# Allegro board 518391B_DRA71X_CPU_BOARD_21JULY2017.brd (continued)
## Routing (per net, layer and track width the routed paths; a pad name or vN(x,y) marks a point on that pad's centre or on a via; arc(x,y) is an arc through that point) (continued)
H_MCASP4_FSX: length 71.1
  TOP w0.127: v2(42.67,82.8) 44.45,82.8 45.09,82.17 45.09,75.95 42.93,73.79 v2(42.93,65.28) ; v2(74.55,71.12) 78.23,71.12 78.9,71.79 81.22,71.79 83.65,74.23 83.65,74.55 83.92,74.82 83.92,76.28 84.2,76.57 84.2,76.96 84.8,77.56 U27.B25
  LY4 w0.133: v2(74.55,71.12) 73.53,71.12 71.83,69.42 71.16,69.42 69.09,67.35 67.86,67.35 64.41,63.9 46.17,63.9 45.3,64.77 43.43,64.77 v2(42.93,65.28)
  BOTTOM w0.127: R256.2 v2(42.67,82.8)
H_MCASP5_ACLKX: length 71.7
  TOP w0.127: U21.7 v2(151.84,121.22)
  LY3 w0.133: v2(111.25,94.49) 112.52,95.76 122.94,95.76 123.23,96.05 125.14,96.05 125.86,96.77 127.51,96.77 128.4,95.88 129.54,95.88 130.05,96.39 131.06,96.39 131.57,95.88 v2(132.33,95.88)
  LY4 w0.133: v2(132.33,95.88) 132.33,97.15 132.84,97.66 132.84,120.78 136.14,124.08 149.73,124.08 151.84,121.98 v2(151.84,121.22)
  BOTTOM w0.127: R429.1 v2(111.25,94.49)
H_MCASP5_AXR0: length 85
  TOP w0.127: U27.AA5 v1(98.49,90.23) ; U21.8 v2(150.84,121.22)
  LY3 w0.133: v1(98.49,90.23) 98.49,93.03 101.6,96.14 106.55,96.14 106.68,96.01 111.25,96.01 111.89,96.65 122.17,96.65 123.06,97.54 128.02,97.54 128.4,97.16 131.57,97.16 131.91,96.82 v2(132.84,96.82)
  LY4 w0.133: v2(150.84,121.22) 150.84,122.34 150.11,123.06 135.64,123.06 133.22,120.65 133.22,97.2 v2(132.84,96.82)
H_MCASP5_AXR1: length 84.8
  TOP w0.102: 101.52,92.44 101.27,92.18 100.57,92.18 100.44,92.06 100.44,91.68 100.29,91.54 99.14,91.54 U27.AC4
  TOP w0.127: v2(101.98,92.9) 101.52,92.44 ; U21.5 v2(153.84,121.22)
  LY3 w0.133: v2(135.76,95.39) 131.56,95.39 131.02,95.93 130.13,95.93 129.7,95.5 128.14,95.5 127.25,96.39 126.11,96.39 124.71,95 121.54,95 121.12,95.42 117.13,95.42 116.71,95 112.52,95 111.51,93.98 108.84,93.98 108.46,94.36 102.87,94.36 101.98,93.47 v2(101.98,92.9)
  LY4 w0.133: v2(153.84,121.22) 153.84,121.2 152.27,119.63 137.79,119.63 136.91,118.75 135.77,118.75 135.64,118.61 135.64,101.98 135.76,101.85 v2(135.76,95.39)
H_MCASP5_FSX: length 89.2
  TOP w0.127: U21.6 v2(152.84,121.22) ; v1(97.84,87.63) U27.U6
  LY3 w0.133: v2(132.72,88.39) 125.72,88.39 125.27,88.84 120.48,88.84 119.52,87.88 113.53,87.88 112.76,88.65 105.3,88.65 105.3,88.65 104.52,88.65 102.74,86.87 98.61,86.87 v1(97.84,87.63)
  LY4 w0.133: v2(132.72,88.39) 132.72,89.53 135.64,92.46 135.64,94.36 135.3,94.7 135.3,119.68 135.64,120.01 151.63,120.01 v2(152.84,121.22)
H_MCASP6_ACLKX_ACLKR: length 65.4
  TOP w0.127: R100.1 93.09,66.67 93.34,66.42 93.34,60.28 96.27,57.36 96.27,50.59 96.48,50.37 96.48,44.41 96.14,44.07 96.14,40 97.16,38.99 97.16,23.12 95.88,21.84 89.66,21.84 89.23,21.41 v2(87.33,21.41)
  LY3 w0.133: v2(87.33,21.41) 87.33,20.28 86.69,19.63 v2(86.69,14.1)
  BOTTOM w0.127: J19.87 v2(86.69,14.1)
H_MCASP6_AXR1: length 78.2
  TOP w0.102: 90.45,76.17 90.45,76.36 90.69,76.59 90.69,77.23 U27.B17
  TOP w0.127: 90.45,76.17 90.45,74.94 89.95,74.44 89.95,73.12 90.68,72.39 90.68,71.73 90.42,71.48 90.42,69.24 90.8,68.86 90.8,68.83 92.33,67.31 92.33,66.17 92.84,65.66 92.84,59.94 94.36,58.42 94.36,56.9 95.25,56.01 95.25,40.05 96.65,38.65 96.65,23.33 95.67,22.35 86.87,22.35 v2(86.61,22.61)
  LY3 w0.133: v2(86.61,22.61) 86.61,20.32 86.09,19.79 v2(86.09,14.6)
  BOTTOM w0.127: J19.88 v2(86.09,14.6)
H_MCASP6_FSX_FSR: length 79.6
  TOP w0.102: U27.B18 90.04,77.23 90.04,76.71 89.95,76.61 89.95,76.17
  TOP w0.127: 89.95,76.17 89.95,75.15 89.44,74.65 89.44,74.24 88.82,73.61 88.82,72.22 89.66,71.37 89.66,69.21 91.44,67.44 91.44,59.06 94.74,55.75 94.74,39.83 96.14,38.44 96.14,23.54 95.46,22.86 88.39,22.86 87.88,23.37 85.85,23.37 v2(85.34,22.86)
  LY3 w0.133: v2(85.34,22.86) 84.96,22.48 84.96,20.95 85.49,20.43 v2(85.49,14.1)
  BOTTOM w0.127: J19.89 v2(85.49,14.1)
H_MCASP7_ACLKX_ACLKR: length 68.5
  TOP w0.127: R102.1 95.63,65.28 97.16,63.75 97.16,58.93 97.54,58.55 97.54,52.32 98.34,51.52 98.34,44.21 97.41,43.29 97.41,40.58 98.55,39.43 98.55,22.58 96.54,20.57 91.69,20.57 91.06,19.94 87.25,19.94 87.12,19.81 v2(83.95,19.81)
  LY3 w0.133: v2(83.69,14.6) 83.69,16.89 83.95,17.14 v2(83.95,19.81)
  BOTTOM w0.127: J19.92 83.69,13.96 83.69,13.97 v2(83.69,14.6)
H_MCASP7_AXR0: length 6.4
  TOP w0.127: v2(82.3,22.61) RJ30.1
  BOTTOM w0.127: J19.31 84.89,20.02 v2(82.3,22.61)
H_MCASP7_AXR1: length 87.6
  TOP w0.127: U27.E17 v1(90.04,79.18)
  LY3 w0.102: 89.79,76.17 89.79,76.58 89.03,77.34 89.03,78.74 89.14,78.85 89.71,78.85 v1(90.04,79.18)
  LY3 w0.133: 89.79,76.17 89.79,69.98 96.77,62.99 96.77,57.06 v2(98.97,54.86) ; v2(84.29,14.1) 84.29,16.09 84.45,16.26 84.45,20.07 84.07,20.45 v2(84.07,22.22)
  BOTTOM w0.127: J19.91 v2(84.29,14.1) ; v2(98.97,54.86) 98.81,54.7 98.81,53.85 103.12,49.53 103.12,48.26 104.52,46.86 104.52,40.89 100.33,36.7 100.33,30.35 96.39,26.42 91.06,26.42 88.27,23.62 86.87,23.62 85.47,22.22 v2(84.07,22.22)
H_MCASP7_FSX_FSR: length 80.8
  TOP w0.127: U27.F16 v1(91.34,79.83)
  LY3 w0.102: 90.42,76.17 90.42,78.92 v1(91.34,79.83)
  LY3 w0.133: v4(92.06,74.42) 91.44,74.42 90.42,75.44 90.42,76.17 ; v2(84.07,25.27) 84.58,24.76 84.58,20.7 84.89,20.4 v2(84.89,14.6)
  BOTTOM w0.127: v2(84.07,25.27) 86.49,25.27 100.33,39.12 100.33,43.05 98.98,44.4 98.98,48.21 95.88,51.31 95.88,58.29 95,59.18 95,63.5 92.52,65.98 92.52,73.98 92.08,74.42 v4(92.06,74.42) ; J19.90 v2(84.89,14.6)
H_MCU_DCAN1_STB: length 97.6
  TOP w0.102: 102.05,85.04 100.44,85.04 U27.P2
  TOP w0.127: 102.05,85.04 102.69,85.67 106.85,85.67 106.89,85.7 109.88,85.7 111.25,84.33 112.78,84.33 114.05,83.06 117.73,83.06 119.89,80.9 125.35,80.9 125.98,81.53 127.89,81.53 128.52,80.9 v2(131.32,80.9) ; R426.1 v2(137.16,26.29)
  LY4 w0.133: v2(131.32,80.9) 131.1,80.68 131.1,70.57 132.59,69.09 132.59,61.09 135,58.67 135.89,58.67 v2(139.95,54.61)
  BOTTOM w0.127: v2(139.95,54.61) 142.88,51.69 142.88,42.67 141.48,41.27 141.48,37.97 139.7,36.19 139.7,34.04 138.05,32.38 138.05,27.05 137.29,26.29 v2(137.16,26.29)
H_MCU_GPIO_1: length 65.4
  TOP w0.127: v2(127.76,80.9) 127.38,81.28 126.11,81.28 125.48,80.64 119.63,80.64 118.36,81.91 115.57,81.91 114.93,82.55 112.27,82.55 110.05,84.77 106.5,84.77 105.85,85.42 102.94,85.42 102.23,84.71 U27.N1
  LY4 w0.133: v2(127.76,80.9) 127.76,76.58 129.8,74.54 129.8,51.06 v2(126.87,48.13)
  BOTTOM w0.127: R327.1 v2(126.87,48.13)
H_MCU_GPIO_2: length 67.7
  TOP w0.127: U27.P1 101.87,85.36 102.43,85.92 106.75,85.92 106.78,85.96 110.13,85.96 111.38,84.71 113.16,84.71 114.43,83.44 117.86,83.44 120.14,81.15 125.1,81.15 125.73,81.79 128.4,81.79 v2(128.78,81.41)
  LY4 w0.133: v2(126.87,47.12) 126.87,47.54 130.06,50.72 130.06,74.79 128.78,76.07 v2(128.78,81.41)
  BOTTOM w0.127: R331.1 v2(126.87,47.12)
H_MCU_GPIO_3: length 76.9
  TOP w0.127: U27.N3 v1(99.79,84.38)
  LY3 w0.133: v1(99.79,84.38) 100.1,84.07 100.71,84.07 102.15,82.64 105.93,82.64 106.37,82.2 111.67,82.2 112.27,82.8 112.27,83.31 112.78,83.82 113.54,83.82 113.92,83.44 118.36,83.44 120.4,81.41 124.97,81.41 127.13,83.57 v2(128.78,83.57)
  LY4 w0.133: v2(128.78,83.57) 129.79,82.55 129.79,77.98 129.29,77.47 129.29,76.2 130.32,75.16 130.32,50.6 127.51,47.79 127.51,46.35 126.87,45.72 126.62,45.72 v2(125.98,45.08)
  BOTTOM w0.127: R335.1 127.38,46.1 127,45.72 126.62,45.72 v2(125.98,45.08)
H_MCU_GPIO_4: length 77.1
  TOP w0.127: U27.N4 v1(99.14,84.38)
  LY3 w0.133: v1(99.14,84.38) 99.51,84.76 100.54,84.76 101.73,83.57 104.77,83.57 105.15,83.19 105.92,83.19 106.05,83.31 110.36,83.31 111.38,84.33 113.66,84.33 114.17,83.82 118.62,83.82 120.65,81.79 124.71,81.79 127.25,84.33 v2(129.41,84.33)
  LY4 w0.133: v2(129.41,84.33) 130.18,83.57 130.18,77.6 129.67,77.09 129.67,76.45 130.58,75.54 130.58,49.43 129.79,48.64 129.03,48.64 127.77,47.38 127.77,45.98 v2(126.87,45.08)
  BOTTOM w0.127: R341.1 v2(126.87,45.08)
H_MMC1_CLK: length 67
  TOP w0.127: v2(149.61,89.03) 149.35,88.77 140.84,88.77 139.19,90.42 136.4,90.42 134.87,88.9 132.63,88.9 131.07,87.34 119.6,87.34 118.75,86.49 R66.1
  LY4 w0.133: v2(149.48,113.92) 149.48,112.9 150.75,111.63 150.75,106.43 151.38,105.79 151.38,102.23 149.22,100.08 149.22,94.74 149.86,94.11 149.86,89.28 v2(149.61,89.03)
  BOTTOM w0.127: RU1.12 149.41,113.85 v2(149.48,113.92) R226.2
H_MMC1_CMD: length 76.7
  TOP w0.127: U27.V4 v1(99.14,88.28)
  LY3 w0.133: v2(146.18,89.53) 145.67,89.03 143.64,89.03 141.99,90.68 135.25,90.68 135,90.42 123.57,90.42 122.84,89.7 114.08,89.7 114.05,89.66 103,89.66 101.22,87.88 99.54,87.88 v1(99.14,88.28)
  LY4 w0.133: v2(146.18,89.53) 146.18,92.46 146.59,92.87 146.59,99.98 147.11,100.5 147.11,111.55 147.46,111.9 v2(147.46,113.65)
  BOTTOM w0.127: R227.2 147.45,113.66 v2(147.46,113.65) RU1.9
H_MMC1_D0: length 74.4
  TOP w0.127: v1(99.79,88.28) U27.V3
  LY3 w0.133: v2(144.78,89.53) 143.26,91.06 135,91.06 134.75,90.8 123.19,90.8 122.94,91.06 116.17,91.06 116.13,91.02 115.78,91.02 115.73,91.06 113.79,91.06 113.41,90.68 106.3,90.68 105.79,90.17 103,90.17 101.11,88.28 v1(99.79,88.28)
  LY4 w0.133: v2(143.45,105.03) 143.45,103.66 143.61,103.5 145.13,103.5 145.29,103.35 145.29,103.13 145.13,102.97 144.79,102.97 144.65,102.84 144.65,100.18 144.81,100.03 145.13,100.03 145.29,99.87 145.29,99.65 145.13,99.49 144.81,99.49 144.65,99.34 144.65,99.12 144.81,98.96 145.13,98.96 145.29,98.8 145.29,98.58 145.13,98.43 144.81,98.43 144.65,98.27 144.65,98.01 144.79,97.88 145,97.88 145.16,97.72 145.16,97.5 145,97.34 144.56,97.34 144.4,97.19 144.4,96.97 144.56,96.81 145,96.81 145.16,96.65 145.16,96.43 145,96.28 144.56,96.28 144.4,96.12 144.4,95.9 144.56,95.74 145,95.74 145.16,95.59 145.16,95.37 145,95.21 144.56,95.21 144.4,95.05 144.4,94.83 144.56,94.68 145,94.68 145.16,94.52 145.16,94.3 145,94.14 144.56,94.14 144.4,93.99 144.4,93.73 144.65,93.47 144.65,92.71 145.29,92.07 145.29,90.04 v2(144.78,89.53)
  BOTTOM w0.127: RU2.4 v2(143.45,105.03) 143.45,104.47 143.38,104.39 R228.2
H_MMC1_D1: length 79.5
  TOP w0.102: 101.52,88.51 101.3,88.29 100.44,88.29 U27.V2
  TOP w0.127: 101.52,88.51 112.13,88.51 113.39,87.25 118.36,87.25 119.13,88.01 121.29,88.01 121.54,88.27 130.56,88.27 132.59,90.3 135.13,90.3 135.76,90.93 142.49,90.93 v2(142.88,90.55)
  LY4 w0.133: v2(141.5,104.8) 141.5,102.97 141.99,102.49 141.99,99.35 142.14,99.2 143.63,99.2 143.76,99.06 143.76,98.8 143.63,98.66 142.14,98.66 141.99,98.51 141.99,98.29 142.14,98.13 143.73,98.13 143.89,97.97 143.89,97.75 143.73,97.6 142.14,97.6 141.99,97.44 141.99,97.22 142.14,97.06 143.73,97.06 143.89,96.91 143.89,96.69 143.73,96.53 142.14,96.53 141.99,96.37 141.99,96.15 142.14,96 143.73,96 143.89,95.84 143.89,95.62 143.73,95.46 142.14,95.46 141.99,95.31 141.99,95.09 142.14,94.93 143.73,94.93 143.89,94.77 143.89,94.55 143.73,94.4 142.14,94.4 141.99,94.24 141.99,93.98 142.88,93.09 v2(142.88,90.55)
  BOTTOM w0.127: R230.2 141.48,104.78 v2(141.5,104.8) RU2.7
H_MMC1_D2: length 81
  TOP w0.127: U27.W1 101.19,88.61 101.35,88.77 112.4,88.77 113.66,87.5 118.11,87.5 118.87,88.27 121.03,88.27 121.41,88.65 121.78,88.65 121.93,88.79 121.93,89.01 122.08,89.15 122.29,89.15 122.44,89.01 122.44,88.79 122.58,88.65 122.79,88.65 122.94,88.79 122.94,89.01 123.09,89.15 123.3,89.15 123.45,89.01 123.45,88.79 123.6,88.65 123.81,88.65 123.96,88.79 123.96,89.01 124.11,89.15 124.32,89.15 124.47,89.01 124.47,88.79 124.62,88.65 124.83,88.65 124.98,88.79 124.98,89.01 125.12,89.15 125.33,89.15 125.48,89.01 125.48,88.79 125.63,88.65 125.84,88.65 125.99,88.79 125.99,89.01 126.14,89.15 126.35,89.15 126.5,89.01 126.5,88.79 126.65,88.65 128.05,88.65 128.2,88.79 128.2,89.51 128.35,89.66 128.56,89.66 128.71,89.51 128.71,88.79 128.86,88.65 129.07,88.65 129.22,88.79 129.22,89.51 129.37,89.66 129.58,89.66 129.73,89.51 129.73,88.79 129.88,88.65 130.3,88.65 132.21,90.55 134.87,90.55 135.51,91.19 143,91.19 143.64,90.55 148.72,90.55 v2(149.35,89.92)
  LY4 w0.133: v2(149.35,89.92) 149.35,90.8 149.6,91.05 149.6,93.61 148.84,94.36 148.84,97.69 148.69,97.84 147.73,97.84 147.57,98 147.57,98.22 147.73,98.38 148.69,98.38 148.84,98.53 148.84,98.75 148.69,98.91 147.73,98.91 147.57,99.07 147.57,99.29 147.73,99.44 148.69,99.44 148.84,99.6 148.84,100.06 150.69,101.91 150.69,104.07 v2(150.06,104.7)
  BOTTOM w0.127: R231.2 150.11,104.65 v2(150.06,104.7) RU1.4
H_MMC1_D3: length 80.1
  TOP w0.127: v2(147.19,89.53) 146.69,89.03 143.51,89.03 142.62,89.92 141.99,89.92 141.22,90.68 136.02,90.68 135.25,89.92 132.84,89.92 130.68,87.76 119.38,87.76 118.62,86.99 113.16,86.99 111.89,88.26 101.72,88.26 101.42,87.96 U27.V1
  LY4 w0.133: v2(148.11,104.93) 148.11,103.35 148.21,103.25 148.21,100.84 147.07,99.69 147.07,97.47 147.22,97.32 148.18,97.32 148.34,97.16 148.34,96.94 148.18,96.78 147.22,96.78 147.07,96.63 147.07,96.41 147.22,96.25 148.18,96.25 148.34,96.09 148.34,95.87 148.18,95.72 147.22,95.72 147.07,95.56 147.07,95.34 147.22,95.18 148.18,95.18 148.34,95.03 148.34,94.81 148.18,94.65 147.22,94.65 147.07,94.49 147.07,94.23 147.59,93.71 147.59,93.65 147.75,93.49 148.43,93.49 148.59,93.33 148.59,93.11 148.06,92.58 146.94,92.58 146.72,92.36 146.72,92.17 146.94,91.95 147.7,91.95 147.95,91.69 147.95,91.19 147.7,90.93 147.07,90.93 146.81,90.68 146.81,90.42 147.03,90.21 147.69,90.21 147.94,89.96 147.94,89.78 147.69,89.53 v2(147.19,89.53)
  BOTTOM w0.127: R229.2 148.08,104.9 v2(148.11,104.93) RU1.7
H_MMC1_SDCD: length 84.4
  TOP w0.127: U27.U5 v1(98.49,87.64)
  LY3 w0.133: v2(129.03,125.73) 130.56,127.25 141.6,127.25 v2(143.13,125.73) ; v2(127.63,89.41) 127.37,89.15 114.27,89.15 114.26,89.14 103.75,89.14 101.85,87.25 98.88,87.25 v1(98.49,87.64)
  LY4 w0.133: v2(129.03,125.73) 128.02,124.71 128.02,89.79 v2(127.63,89.41)
  BOTTOM w0.127: R410.2 v2(143.13,125.73) R411.1
H_MMC1_SDWP: length 69.5
  TOP w0.127: U27.V5 v1(98.49,88.28)
  LY3 w0.133: v1(98.49,88.28) 99.27,87.5 101.34,87.5 103.24,89.4 114.15,89.4 114.16,89.41 123.7,89.41 124.45,90.16 135.11,90.16 135.12,90.17 135.38,90.17 135.63,90.42 140.6,90.42 v2(140.84,90.17)
  LY4 w0.133: v2(140.84,90.17) 140.84,90.81 140.63,91.02 140.63,94.02 140.85,94.24 v2(140.85,113.66)
  BOTTOM w0.127: RU2.9 v2(140.85,113.66)
H_MMC1_SELN: length 90.9
  TOP w0.102: 101.52,84.38 100.44,84.38 U27.N2
  TOP w0.127: v2(146.35,78.99) 145.58,78.23 136.14,78.23 133.99,80.39 119.51,80.39 118.62,81.28 105.46,81.28 102.36,84.38 101.52,84.38
  LY3 w0.133: v2(152.02,107.7) 151.64,107.31 145.8,107.31 145.43,107.69 v2(145.4,107.69)
  LY4 w0.133: v2(146.35,78.99) 146.35,80.35 145.67,81.03 145.67,101.22 146.22,101.77 146.22,103.59 145.41,104.39 145.41,107.68 v2(145.4,107.69)
  BOTTOM w0.127: v2(152.02,107.7) 152.02,106.37 RU1.1 152.01,104.76 151.76,104.52 R425.1 ; RU2.1 v2(145.4,107.69)
H_NMIN_DSP: length 16.2
  TOP w0.102: 84.4,82.8 84.47,82.8 84.76,83.09 85.49,83.09 U27.L24
  TOP w0.127: 84.4,82.8 82.59,82.8 81.07,81.28 78.78,81.28 76.66,79.16 76.53,79.16 75.48,78.1 73.03,78.1 R71.2
H_PMIC_INTN: length 125.9
  TOP w0.127: U32.26 82.97,51.85 82.47,51.36 81.76,51.36 81.46,51.05 77.47,51.05 v2(77.34,51.18) ; U27.AB10 v1(95.24,90.88) ; v2(113.03,56.26) 113.03,58.29 112.39,58.93 v2(112.39,63.25)
  LY3 w0.133: v2(96.77,96.39) 98.04,97.66 106.55,97.66 106.72,97.83 v2(118.87,97.83) ; v2(113.03,56.26) 112.14,55.37 111.51,55.37 106.92,50.79 96.76,50.79 96.39,50.42 89.03,50.42 88.13,51.31 88.13,51.82 87.78,52.18 82.91,52.18 81.91,51.18 v2(77.34,51.18)
  LY4 w0.133: v2(112.39,63.25) 115.95,63.25 118.62,65.91 118.62,77.72 116.97,79.38 116.97,83.44 117.73,84.2 117.73,89.03 116.84,89.92 116.84,90.8 118.87,92.83 118.87,97.78 118.87,97.79 v2(118.87,97.83) ; v1(95.24,90.88) 95.7,91.34 95.7,94.43 96.77,95.5 v2(96.77,96.39)
  BOTTOM w0.127: v2(96.77,96.39) 97.03,96.14 R236.1
H_PORZ: length 106.7
  TOP w0.127: U27.F19 v1(89.39,79.83) ; v2(85.34,68.96) 85.34,68.07 85.98,67.44 85.98,65.91 86.61,65.28 89.68,65.28 90.42,64.54 90.42,58.42 93.73,55.12 93.73,52.79 93.56,52.62 v2(93.56,50.93) 93.56,49.95 93.73,49.78 93.73,41.4 93.47,41.15 v2(93.47,38.99) ; TP40.1 74.88,51.74 78.56,51.74 78.94,51.36 81.38,51.36 81.64,51.61 82.22,51.61 82.47,51.86 U32.25 ; U40.3 116.47,41.39 115.06,42.8 113.41,42.8 111.38,40.77 v2(111.38,37.68)
  LY3 w0.133: TP40.1 75.18,52.19 77.98,52.19 78.49,51.69 81.91,51.69 82.66,52.44 87.91,52.44 88.39,51.96 88.39,51.56 89.03,50.93 v2(93.56,50.93) ; v2(111.38,37.68) 110.15,37.68 109.09,38.73 96.52,38.73 96.27,38.99 v2(93.47,38.99)
  BOTTOM w0.102: 87.58,76.17 88.82,77.42 88.82,79.27 v1(89.39,79.83)
  BOTTOM w0.127: 87.58,76.17 85.85,74.45 85.85,69.47 v2(85.34,68.96)
H_RSTOUTN: length 150.4
  TOP w0.127: TP36.1 74.55,62.1 74.93,61.72 79.88,61.72 81.41,60.2 81.41,59.56 81.69,59.28 U32.13 ; TP36.1 74.55,69.18 v2(74.42,69.3) ; TP36.1 R104.2 ; U27.E20 v1(88.09,79.18)
  LY3 w0.133: v2(145.92,62.61) 145.03,63.5 137.29,63.5 136.65,62.86 134.62,62.86 134.51,62.98 124.85,62.98 124.21,63.63 123.06,63.63 122.86,63.83 122,63.83 121.78,63.62 121.78,63.24 121.54,62.99 113.67,62.99 v2(111.89,64.77)
  LY4 w0.133: v2(111.89,64.77) 106.3,64.77 105.41,63.88 76.96,63.88 76.33,63.25 TP36.1 ; v2(74.42,69.3) 74.42,69.84 76.33,71.74 76.33,72.64 76.88,73.2 81.15,73.2 81.23,73.28 81.85,73.28 82.26,73.69 82.49,73.69 83.4,74.6 84.03,74.6 84.6,75.16 85.32,75.16 85.32,75.16 85.45,75.16 86.49,76.2 86.49,76.33 88.46,78.3 88.46,78.81 v1(88.09,79.18) ; v2(141.66,92.64) 141.66,82.75 144.78,79.63 144.78,76.2 146.18,74.8 146.18,70.48 145.8,70.1 145.8,63.25 145.92,63.12 v2(145.92,62.61)
  BOTTOM w0.127: J21.29 v2(141.66,92.64)
  BOTTOM w0.14: U54.1 115.3,64.02 114.55,64.77 v2(111.89,64.77)
H_SPI1_CS0: length 69.7
  TOP w0.102: 84.79,76.17 84.79,77.06 84.96,77.23 85.32,77.23 85.64,77.56 U27.B24
  TOP w0.127: 84.79,76.17 84.79,75.32 83.91,74.45 83.91,74.12 81.32,71.54 79.33,71.54 78.44,70.66 76.18,70.66 76.01,70.48 74.24,70.48 74.08,70.65 v2(74.04,70.65) ; v2(40.39,69.72) 40.39,67.82 40.13,67.56 40.13,62.86 37.59,60.32 37.59,57.4 36.58,56.39 34.16,56.39 33.07,55.29 U36.43
  LY3 w0.133: v2(74.04,70.65) 73.19,71.5 65.28,71.5 64.43,70.65 41.31,70.65 v2(40.39,69.72)
H_SPI1_CS1: length 51.4
  TOP w0.127: v2(72.39,72.35) 72.95,71.79 77.51,71.79 77.85,72.14 77.85,72.64 78.14,72.94 80.46,72.94 83.01,75.49 83.01,77 83.41,77.4 83.88,77.4 84.69,78.21 U27.C25 ; U34.23 51.91,53.3 54.1,55.5 54.99,55.5 55.5,56.01 55.5,64.52 v2(55.88,64.9)
  LY4 w0.133: v2(55.88,64.9) 56.82,65.84 62.92,65.84 66.17,69.09 68.62,69.09 69.6,70.07 69.6,70.51 71.69,72.6 72.14,72.6 v2(72.39,72.35)
H_SPI1_D0: length 71.3
  TOP w0.127: v2(73.53,72.35) 74.08,72.9 75.48,72.9 75.91,72.9 76.45,73.44 79.29,73.44 81.47,75.63 82.11,75.63 82.42,75.95 82.42,77.13 83.27,77.98 83.69,77.98 84.57,78.86 U27.D25 ; v2(57.4,64.9) 56.26,63.75 56.26,56.01 52.96,52.7 52.7,52.7 52.3,52.3 v2(52.09,52.3) U34.21 ; U36.41 v2(33.08,53.78)
  LY4 w0.133: v2(57.4,64.9) 57.83,65.32 64.18,65.32 67.25,68.39 68.66,68.39 70.12,69.86 70.12,70 71.71,71.59 72.24,71.59 72.69,72.03 72.69,72.03 73.01,72.35 73.53,72.35 v2(73.53,72.35)
  BOTTOM w0.127: v2(33.08,53.78) 40.06,53.78 40.51,54.23 v2(41.53,54.23) 49.78,54.23 51.71,52.3 v2(52.09,52.3)
H_SPI1_D1: length 71.1
  TOP w0.102: 84.4,78.31 84.63,78.53 85.49,78.53 U27.D24
  TOP w0.127: U34.20 52.57,51.8 v2(52.96,52.2) 56.64,55.88 56.64,63.37 v2(58.17,64.9) ; v2(74.3,72.26) 75.63,72.26 76.56,73.19 79.53,73.19 81.71,75.38 82.21,75.38 82.76,75.92 82.76,77.11 83.37,77.72 83.82,77.72 84.4,78.31 ; U36.40 v2(34.96,53.28)
  LY4 w0.133: v2(58.17,64.9) 58.33,65.06 64.28,65.06 67.36,68.13 68.77,68.13 70.38,69.75 70.38,69.89 71.82,71.33 72.35,71.33 72.95,71.93 73.7,71.93 74.04,72.26 v2(74.3,72.26)
  BOTTOM w0.127: v2(52.96,52.2) 52.65,51.88 51.62,51.88 49.78,53.72 v2(40.89,53.72) 40.45,53.28 v2(34.96,53.28)
H_SPI1_SCLK: length 60.8
  TOP w0.127: U34.22 52.17,52.8 v2(52.45,53.09) 52.96,53.09 55.88,56.01 55.88,64.13 v2(56.64,64.9) ; U36.42 v2(34.96,54.28) ; v2(71.75,72.01) 72.22,71.54 78.02,71.54 78.74,72.26 R81.2
  LY4 w0.133: v2(56.64,64.9) 57.32,65.58 64.06,65.58 67.13,68.65 68.55,68.65 69.86,69.96 69.86,70.12 v2(71.75,72.01)
  BOTTOM w0.127: v2(52.45,53.09) 52.2,52.83 51.82,52.83 49.91,54.74 v2(42.16,54.74) 40.39,54.74 39.93,54.28 v2(34.96,54.28)
H_SPI2_CS0: length 87.4
  TOP w0.102: 84.4,79.77 84.47,79.83 85.49,79.83 U27.F24
  TOP w0.127: 84.4,79.77 83.38,78.74 82.91,78.74 81.51,77.34 79.25,77.34 78.66,76.76 78.66,76 76.87,74.21 76.14,74.21 76.1,74.17 76.09,74.17 75.59,73.66 73.6,73.66 73.22,73.28 71.54,73.28 70.74,72.47 70.74,69.89 71.12,69.51 71.12,64.3 70.74,63.92 70.74,63.29 69.22,61.76 69.22,53.85 72.14,50.93 v2(72.14,44.07)
  LY3 w0.133: v2(72.14,44.07) 73.15,43.05 73.15,40.51 76.45,37.21 76.45,36.83 79.63,33.65 79.63,30.61 87.76,22.48 87.76,20.07 87.38,19.68 87.38,18.41 87.89,17.9 v2(87.89,14.1)
  BOTTOM w0.127: J19.85 v2(87.89,14.1)
H_SPI2_D0: length 89.1
  TOP w0.102: U27.G24 85.5,80.49 85.5,80.49 85.49,80.48 84.4,80.48
  TOP w0.127: 84.4,80.48 84.29,80.48 83.06,79.25 79.65,79.25 78.74,78.34 78.74,77.79 77.22,76.26 77.22,75.56 76.37,74.71 75.93,74.71 75.89,74.68 75.88,74.68 75.38,74.17 73.39,74.17 73.01,73.79 71.33,73.79 70.23,72.68 70.23,69.68 70.61,69.3 70.61,64.51 70.23,64.13 70.23,63.5 68.71,61.97 68.71,53.59 71.37,50.93 71.37,47.62 v2(71.25,47.5)
  LY3 w0.133: v2(89.09,14.03) 89.03,14.09 89.03,18.16 88.9,18.29 88.9,22.35 80.39,30.86 80.39,34.92 73.91,41.4 73.91,43.56 71.75,45.72 71.75,46.99 v2(71.25,47.5)
  BOTTOM w0.127: J19.83 v2(89.09,14.03)
H_SPI2_D1: length 87.8
  TOP w0.127: U27.F25 84.35,80.16 83.19,78.99 79.76,78.99 78.99,78.23 78.99,77.68 77.47,76.16 77.47,75.44 76.49,74.46 76.03,74.46 75.99,74.42 75.99,74.42 75.48,73.91 73.49,73.91 73.11,73.53 71.44,73.53 70.48,72.58 70.48,69.79 70.87,69.41 70.87,64.41 70.48,64.03 70.48,63.39 68.96,61.87 68.96,53.72 71.75,50.93 71.75,46.99 v2(71.25,46.48)
  LY3 w0.133: v2(88.49,14.57) 88.52,14.6 88.52,22.22 80.01,30.73 80.01,34.8 73.53,41.27 73.53,43.43 71.25,45.72 v2(71.25,46.48)
  BOTTOM w0.127: J19.84 v2(88.49,14.57)
H_SPI2_SCLK: length 74.4
  TOP w0.127: v2(70.87,48.89) 70.87,51.05 68.45,53.47 68.45,62.08 69.98,63.6 69.98,64.24 70.36,64.62 70.36,69.2 69.98,69.58 69.98,72.79 71.23,74.04 71.44,74.04 72.77,74.04 73.41,74.68 R77.2
  LY3 w0.133: v2(70.87,48.89) 72.14,47.62 72.14,45.85 74.17,43.81 74.17,41.65 80.77,35.05 80.77,30.99 89.28,22.48 89.28,18.67 89.66,18.29 89.66,14.6 v2(89.69,14.58)
  BOTTOM w0.127: J19.82 v2(89.69,14.58)
H_SPI4_CS0: length 192
  TOP w0.127: v2(128.78,82.59) 125.39,82.59 124.46,81.66 120.65,81.66 118.11,84.2 114.55,84.2 112.65,86.11 111.63,86.11 110.66,87.08 106.24,87.08 106.22,87.07 105.74,87.07 105.16,86.49 101.98,86.49 101.5,86.01 U27.R1
  LY3 w0.133: v2(128.78,82.59) 131.15,82.59 135.52,78.22 153.84,78.22 156.36,75.69 165.1,75.69 167.39,73.41 167.39,64.77 164.08,61.47 164.08,60.45 163.5,59.87 163.5,57.96 161.04,55.5 161.04,54.48 160.15,53.59 160.15,43.56 161.42,42.29 161.42,26.67 152.53,17.78 117.47,17.78 112.27,12.57 106.17,12.57 104.14,14.6 v2(101.68,14.6)
  BOTTOM w0.127: J19.62 v2(101.68,14.6)
H_SPI4_CS1: length 200.1
  TOP w0.127: U27.N6 v1(97.84,84.38)
  LY3 w0.133: v2(100.71,14.1) 104.04,14.1 105.94,12.19 112.37,12.19 113.92,13.74 142.77,13.74 144.4,15.37 144.4,15.87 144.97,16.45 153.35,16.45 157.48,20.57 161.54,20.57 166.37,25.4 166.37,28.19 168.14,29.96 168.14,52.59 167.77,52.96 167.77,73.46 165.15,76.07 156.59,76.07 154.18,78.48 136.4,78.48 133.99,80.9 133.99,81.41 132.33,83.06 127.13,83.06 125.09,81.03 120.14,81.03 118.11,83.06 113.41,83.06 v2(113.16,83.31)
  LY4 w0.133: v2(113.16,83.31) 112.14,84.33 105.41,84.33 105.12,84.04 102.19,84.04 101.4,84.84 98.29,84.84 v1(97.84,84.38)
  BOTTOM w0.127: J19.64 100.46,12.81 100.46,13.84 v2(100.71,14.1)
H_SPI4_CS2: length 205.6
  TOP w0.102: U27.T4 99.12,86.36 101.34,86.36 101.52,86.54
  TOP w0.127: v4(105.16,87.14) 105.16,87.12 104.78,86.74 101.73,86.74 101.52,86.54
  LY3 w0.133: v2(99.85,14.12) 100.39,13.59 101.85,13.59 104.13,11.31 113.03,11.31 114.68,12.96 144.9,12.96 145.92,11.94 151.76,11.94 156.58,16.76 159.13,16.76 161.8,19.43 162.81,19.43 168.9,25.52 168.9,26.82 168.14,27.58 168.14,28.68 168.92,29.46 168.92,74.8 164.21,79.5 148.59,79.5 141.57,86.52 135.98,86.52 135.64,86.87 126.36,86.87 124.91,88.32 120.83,88.32 119.88,87.36 113.18,87.36 113.16,87.38 112.9,87.38 112.27,88.01 105.66,88.01 105.16,87.5 v4(105.16,87.14)
  BOTTOM w0.127: J19.65 99.88,14.1 v2(99.85,14.12)
H_SPI4_CS3: length 208.8
  TOP w0.102: 101.52,87.1 101.42,86.99 98.5,86.99 U27.T5
  TOP w0.127: v4(104.52,87.5) 104.27,87.75 102.18,87.75 101.52,87.1
  LY3 w0.133: v2(99.12,14.03) 100.08,13.08 101.6,13.08 103.63,11.05 113.28,11.05 114.94,12.7 144.53,12.7 145.67,11.56 154.56,11.56 162.05,19.05 163.19,19.05 169.29,25.15 169.29,26.8 168.4,27.69 168.4,28.57 169.29,29.46 169.29,74.93 164.34,79.88 148.84,79.88 140.33,88.39 135,88.39 134.53,87.93 125.82,87.93 125.16,88.58 120.59,88.58 119.63,87.62 113.29,87.62 112.52,88.39 105.41,88.39 v4(104.52,87.5)
  BOTTOM w0.127: J19.66 99.28,13.88 v2(99.12,14.03)
H_SPI4_D0: length 186.7
  TOP w0.102: 101.52,85.69 100.44,85.69 U27.R2
  TOP w0.127: 101.52,85.69 101.69,85.69 102.18,86.18 106.22,86.18 106.25,86.21 110.64,86.21 111.13,85.72 112.52,85.72 114.43,83.82 117.98,83.82 120.4,81.41 124.84,81.41 125.6,82.17 129.03,82.17 v2(129.29,81.91)
  LY3 w0.133: v2(129.29,81.91) 133.24,77.96 153.31,77.96 155.96,75.31 163.92,75.31 167,72.22 167,65.02 162.81,60.83 162.81,57.91 160.53,55.63 160.53,54.61 159.77,53.85 159.77,43.18 160.91,42.04 160.91,27.18 152.78,19.05 146.05,19.05 145.67,18.67 143.89,18.67 143.38,19.18 138.18,19.18 137.16,18.16 114.43,18.16 113.28,19.3 102.87,19.3 v2(102.62,19.56)
  BOTTOM w0.127: v2(102.62,19.56) 102.28,19.22 J19.60
H_SPI4_D1: length 196.3
  TOP w0.127: U27.P3 v1(99.79,85.68)
  LY3 w0.133: v1(99.79,85.68) 106.64,85.68 106.8,85.85 112.02,85.85 112.52,85.34 119.51,85.34 121.67,87.5 124.21,87.5 126.87,84.84 131.95,84.84 132.33,84.45 132.84,84.45 135.64,81.66 135.64,81.28 136.4,80.52 145.92,80.52 147.7,78.74 163.96,78.74 168.15,74.55 168.15,53.59 168.4,53.35 168.4,29.67 167.51,28.78 167.51,25.65 162.05,20.19 157.99,20.19 152.91,15.11 146.05,15.11 145.55,14.61 144.15,14.61 143.02,13.48 114.19,13.48 112.54,11.83 105.61,11.83 v2(104.65,12.79)
  BOTTOM w0.127: J19.61 v2(104.65,12.79)
H_SPI4_SCLK: length 187.8
  TOP w0.127: v2(116.84,85.85) 116.82,85.85 R183.1 ; v2(101.73,19.43) 103.12,18.03 v2(103.12,13.59)
  LY3 w0.133: v2(116.84,85.85) 119.38,85.85 121.28,87.76 121.3,87.76 121.3,87.76 124.31,87.76 124.32,87.76 124.46,87.76 127,85.22 132.21,85.22 132.59,84.84 133.86,84.84 136.27,82.42 144.65,82.42 147.95,79.12 164.08,79.12 168.53,74.68 168.53,54.48 168.66,54.36 168.66,29.57 167.77,28.68 167.77,25.4 162.18,19.81 160.4,19.81 158.5,17.91 156.59,17.91 152.59,13.91 146.11,13.91 145.8,14.22 144.4,14.22 143.4,13.22 114.45,13.22 112.8,11.57 104.51,11.57 103.12,12.95 v2(103.12,13.59)
  BOTTOM w0.127: J19.59 101.68,19.38 v2(101.73,19.43)
H_UART1_RXD: length 123.9
  TOP w0.127: v2(67.73,64.01) 67.31,64.43 67.31,73.51 69.72,75.92 69.72,77.34 70.36,77.98 72.52,77.98 72.9,78.36 75.37,78.36 76.43,79.41 76.56,79.41 78.68,81.53 80.96,81.53 82.48,83.05 84.42,83.05 84.78,83.41 U27.L25
  LY3 w0.133: v2(131.57,38.99) 131.57,37.46 130.81,36.7 130.81,35.31 127.76,32.26 122.68,32.26 121.29,30.87 101.59,30.87 100.97,31.5 86.75,31.5 75.93,42.32 75.93,45.48 74.3,47.12 74.3,48.26 69.48,53.07 69.48,61.71 68.07,63.12 68.07,63.67 v2(67.73,64.01)
  BOTTOM w0.127: R357.1 v2(131.57,38.99)
H_UART1_TXD: length 128
  TOP w0.127: U27.M25 84.75,84.06 84.25,83.56 82.27,83.56 80.75,82.04 78.47,82.04 76.35,79.92 76.21,79.92 75.41,79.12 70.78,79.12 68.8,77.13 68.8,75.4 67.06,73.66 67.06,63.63 v2(67.31,63.37)
  LY3 w0.133: v2(67.31,63.37) 69.09,61.59 69.09,52.96 73.91,48.13 73.91,46.99 75.67,45.23 75.67,42.14 86.7,31.11 100.71,31.11 101.22,30.61 121.92,30.61 123.19,31.88 130.94,31.88 132.21,33.15 132.21,36.74 132.04,36.91 132.04,38.31 v2(132.72,38.99)
  BOTTOM w0.127: R356.1 v2(132.72,38.99)
H_UART3_RXD_BOOT: length 106.3
  TOP w0.127: U27.N22 v1(86.79,84.38)
  LY4 w0.133: v2(46.1,99.44) 45.58,98.92 45.58,97.19 46.07,96.7 46.07,69.4 47.5,67.97 63.14,67.97 65.1,69.93 65.1,70.69 66.41,72 66.41,73.01 70.1,76.71 73.03,76.71 78.11,81.79 80.9,81.79 83.94,84.83 84.51,84.83 84.52,84.84 86.34,84.84 v1(86.79,84.38)
  BOTTOM w0.127: R232.1 23.75,102.74 41.27,102.74 44.58,99.44 v2(46.1,99.44)
H_UART3_TXD_BOOT: length 106.9
  TOP w0.102: 84.4,84.07 84.72,84.38 85.49,84.38 85.49,84.38 U27.N24
  TOP w0.127: R56.2 17.65,98.81 v4(18.01,98.44) ; 84.4,84.07 84.15,83.81 82.04,83.81 80.52,82.3 78.36,82.3 76.24,80.18 76.11,80.18 75.31,79.38 70.68,79.38 68.54,77.24 68.54,75.65 66.93,74.04 v2(65.91,74.04)
  LY4 w0.133: v2(65.91,74.04) 64.52,72.64 64.52,71.89 63.49,70.87 47.75,70.87 46.85,71.77 46.85,97.63 v2(46.69,97.79)
  BOTTOM w0.127: v4(18.01,98.44) 18.67,97.79 19.69,97.79 24.13,102.23 40.64,102.23 45.09,97.79 v2(46.69,97.79)
  BOTTOM w0.14: U52.2 v4(18.01,98.44)
H_UART5_CTSN: length 86.2
  TOP w0.102: 99.46,89.92 U27.AA3
  TOP w0.127: U27.AA3 v1(99.79,90.23) ; U21.62 v2(159.62,112.26)
  LY3 w0.133: v2(154.31,90.55) 153.03,91.82 145.92,91.82 145.29,91.19 144.14,91.19 143.64,91.69 134.62,91.69 134.37,91.44 123.95,91.44 121.92,93.47 121.03,93.47 120.02,94.49 112.65,94.49 111.58,93.42 108.89,93.42 108.33,93.98 103.25,93.98 102.4,93.13 102.4,92.72 101.52,91.84 99.92,90.23 v1(99.79,90.23)
  LY4 w0.133: v2(159.62,112.26) 160.15,111.73 160.15,110.24 160.45,109.93 160.45,95.68 156.72,91.95 155.7,91.95 v2(154.31,90.55)
H_UART5_RTSN: length 86.1
  TOP w0.102: U27.W2 100.44,88.93 101,88.93 101.08,89.02 101.52,89.02
  TOP w0.127: v2(152.65,89.66) 150.5,89.66 149.35,90.8 143.89,90.8 143.26,91.44 135.25,91.44 134.62,90.8 131.83,90.8 131.19,90.17 127.63,90.17 127.13,89.66 121.67,89.66 120.52,88.52 118.62,88.52 117.86,87.76 113.92,87.76 112.66,89.02 101.52,89.02 ; U21.63 v2(159.62,113.26)
  LY4 w0.133: v2(159.62,113.26) 160.53,112.35 160.53,110.36 160.78,110.11 160.78,94.49 155.96,89.66 v2(152.65,89.66)
H_UART5_RXD: length 82.3
  TOP w0.127: U21.60 v2(159.62,110.26) ; U27.Y4 v1(99.14,88.93)
  LY3 w0.133: v2(153.16,90.8) 152.65,91.31 146.18,91.31 145.67,90.8 144.02,90.8 143.5,91.32 134.75,91.32 134.61,91.18 123.45,91.18 121.67,92.96 115.7,92.96 114.81,92.07 103.5,92.07 100.74,89.31 99.51,89.31 v1(99.14,88.93)
  LY4 w0.133: v2(159.62,110.26) 160.06,109.81 160.06,95.93 156.59,92.46 154.81,92.46 v2(153.16,90.8)
H_UART5_TXD: length 80.7
  TOP w0.102: U27.AA2 100.44,90.23 101.52,90.23
  TOP w0.127: v2(152.4,90.8) 150.62,90.8 150.11,91.31 144.4,91.31 143.76,91.95 134.75,91.95 134.37,92.33 133.6,92.33 132.97,91.69 130.81,91.69 130.43,91.31 127.25,91.31 126.75,90.8 121.16,90.8 119.76,89.41 114.3,89.41 113.03,90.68 106.3,90.68 105.85,90.23 101.52,90.23 ; U21.61 v2(159.62,111.26)
  LY4 w0.133: v2(152.4,90.8) 154.43,92.84 156.34,92.84 157.1,93.6 157.1,99.31 157.48,99.69 157.48,103.25 158.5,104.27 158.5,110.14 v2(159.62,111.26)
H_UART9_RXD: length 207.6
  TOP w0.127: R65.2 v2(152.15,87.88) ; U27.L20 v1(88.09,83.73)
  LY3 w0.133: v2(98.3,108.71) 115.44,108.71 120.14,104.01 129.54,104.01 134.24,99.31 148.84,99.31 v2(151.64,96.52)
  LY4 w0.133: v2(151.64,96.52) 151.51,96.39 151.51,88.52 v2(152.15,87.88) ; v1(88.09,83.73) 87.16,82.8 86.94,82.8 86.94,82.81 85.47,82.81 82.55,79.88 79.38,79.88 76.57,77.08 75.43,77.08 72.78,74.43 71.32,74.43 71.31,74.42 71.25,74.42 70.1,73.28 68.72,73.28 67.57,72.13 67.57,70.36 66.94,69.73 65.67,69.73 63.39,67.45 47.28,67.45 45.55,69.18 45.55,96.49 45.06,96.98 45.06,99.37 46.16,100.46 47.06,100.46 52.4,105.81 52.4,106.75 53.03,107.37 84.38,107.37 84.96,107.95 97.54,107.95 v2(98.3,108.71)
H_UART9_TXD: length 194.7
  TOP w0.102: U27.M24 85.49,83.73 85.49,83.73 84.78,83.73 84.4,83.36
  TOP w0.127: R67.2 v2(151.38,86.11) ; v2(69.22,76.71) 69.22,77.19 70.89,78.87 75.52,78.87 76.32,79.67 76.45,79.67 78.57,81.79 80.86,81.79 82.38,83.31 84.35,83.31 84.4,83.36
  LY3 w0.133: v2(99.95,107.06) 116.33,107.06 119.76,103.63 129.16,103.63 133.86,98.93 148.34,98.93 v2(150.75,96.52)
  LY4 w0.133: v2(99.95,107.06) 98.56,105.67 53.74,105.67 47.11,99.04 47.11,72.14 48.01,71.25 63.12,71.25 64.13,72.26 64.13,72.86 67.98,76.71 v2(69.22,76.71) ; v2(151.38,86.11) 151.13,86.36 151.13,96.14 v2(150.75,96.52)
H_USB1_DN: length 69.8
  TOP w0.122: U11.4 125.22,146.77 125.27,146.72 125.27,145.76 v2(125.19,145.67)
  TOP w0.127: U27.AB7 v1(97.19,90.88)
  LY4 w0.102: v1(97.19,90.88) 96.99,91.13 96.39,91.13 96.13,91.39 96.13,93.21 96.12,93.22 96.12,93.24
  LY4 w0.127: 96.12,93.24 96.12,94.35 117.86,116.09 117.86,134.63 125.2,141.97 125.2,145.66 v2(125.19,145.67)
H_USB1_DP: length 69.8
  TOP w0.122: v2(125.99,145.67) 125.55,146.11 125.55,146.62 125.71,146.79 U11.5
  TOP w0.127: U27.AC6 v1(97.19,91.53)
  LY4 w0.102: v1(97.19,91.53) 96.99,91.38 96.49,91.38 96.38,91.49 96.38,93.21 96.4,93.22 96.4,93.24
  LY4 w0.127: 96.4,93.24 96.4,94.24 118.14,115.98 118.14,134.52 125.48,141.86 125.48,145.28 125.6,145.4 125.73,145.4 v2(125.99,145.67)
H_USB1_DRVVBUS: length 73.4
  TOP w0.102: 99.79,93.24 99.79,92.18 U27.AD3
  TOP w0.127: v2(131.7,136.52) 131.7,124.84 130.05,123.19 130.05,117.22 115.44,102.62 113.79,102.62 106.81,95.63 101.98,95.63 99.79,93.44 99.79,93.24 ; R9.1 R8.1 v2(128.27,144.14) R11.1
  BOTTOM w0.127: v2(128.27,144.14) 131.7,140.72 v2(131.7,136.52)
H_USB2_DN: length 86.8
  TOP w0.102: 98.81,92.96 98.81,92.94 98.77,92.91 98.77,92.29 98.49,92.01 98.49,91.54 U27.AC5
  TOP w0.122: 98.81,92.96 98.81,94.11 101.83,97.13 104.11,97.13 126.39,119.41 126.39,120.89 v2(126.65,121.16) ; v2(154.71,142.97) 154.44,143.23 154.44,144.17 154.62,144.35 U12.12
  BOTTOM w0.122: v2(154.71,142.97) 154.44,142.71 154.44,142.45 154.57,142.33 154.87,142.33 154.99,142.2 154.99,141.96 154.87,141.84 154.57,141.84 154.44,141.72 154.44,141.35 153.91,140.82 142.48,140.82 126.39,124.73 126.39,121.42 v2(126.65,121.16)
H_USB2_DP: length 86.8
  TOP w0.102: U27.AB6 97.84,90.88 97.84,91.38 98.23,91.78 98.23,92.12 98.51,92.4 98.51,93.01 98.53,93.03
  TOP w0.122: U12.11 153.99,144.35 154.17,144.17 154.17,143.23 v2(153.9,142.97) ; 98.53,93.03 98.53,94.22 101.71,97.41 104,97.41 126.11,119.52 126.11,120.89 v2(125.85,121.16)
  BOTTOM w0.122: v2(153.9,142.97) 154.17,142.71 154.17,141.47 153.8,141.1 142.37,141.1 126.11,124.84 126.11,121.42 v2(125.85,121.16)
H_USB2_DRVVBUS: length 114.4
  TOP w0.127: R13.1 163.83,142.37 162.81,141.35 v2(161.8,141.35) Q2.2 ; v1(97.84,90.23) U27.AA6
  LY3 w0.133: v2(129.29,97.79) 129.03,98.04 123.06,98.04 122.05,97.03 111.51,97.03 110.87,96.39 106.93,96.39 106.68,96.65 101.22,96.65 97.84,93.27 v1(97.84,90.23)
  LY4 w0.133: v2(143.7,139.76) 139.7,135.76 132.59,135.76 131.06,134.24 131.06,125.09 129.29,123.32 v2(129.29,97.79)
  BOTTOM w0.127: v2(143.7,139.76) 145.8,137.67 156.08,137.67 159.77,141.35 v2(161.8,141.35)
H_USB3_RXN: length 72.4
  TOP w0.122: FL5.4 130.96,149.17 130.71,148.92 130.71,148.67 130.83,148.55 131.12,148.55 131.25,148.43 131.25,148.18 131.12,148.06 130.83,148.06 130.71,147.94 130.71,141.11 124.46,134.86 124.46,120.01 103.28,98.83 103.28,98.44 102.86,98.02 101.7,98.02 98.12,94.44 98.12,93.05 98.12,92.96 98.16,92.92 98.16,92.85 U27.AE5
H_USB3_RXP: length 72.3
  TOP w0.102: 97.84,92.92 97.84,92.85 97.84,92.19 U27.AD6
  TOP w0.122: FL5.1 130.15,149.17 130.43,148.89 130.43,141.22 124.18,134.98 124.18,120.13 103,98.95 103,98.55 102.74,98.3 101.59,98.3 97.84,94.56 97.84,93.05 97.84,92.92
H_USB3_TXN: length 71.4
  TOP w0.122: C14.1 133.11,146.7 133.11,146.45 133.23,146.33 133.52,146.33 133.64,146.2 133.64,145.96 133.52,145.84 133.23,145.84 133.11,145.72 133.11,140.21 128.02,135.11 128.02,118.87 105.38,96.24 102.08,96.24 99.43,93.59 99.43,92.95 99.46,92.91 U27.AE3
H_USB3_TXP: length 71.4
  TOP w0.102: 99.15,92.95 99.12,92.91 99.12,92.17 U27.AD4
  TOP w0.122: C13.1 132.83,146.7 132.83,140.32 127.74,135.23 127.74,118.99 105.27,96.52 101.97,96.52 99.15,93.71 99.15,92.95
H_XREF_CLK0: length 82.7
  TOP w0.127: R72.2 73.15,76.45 72.9,76.2 70.99,76.2 67.82,73.03 67.82,69.21 68.28,68.75 68.28,64.78 v2(68.28,64.77) ; R164.2 v2(95.12,11.43)
  LY3 w0.133: v2(95.12,11.43) 95.12,12.57 92.96,14.73 92.96,18.8 92.46,19.3 92.46,23.37 82.3,33.53 82.3,35.15 75.41,42.04 75.41,44.98 73.53,46.86 73.53,48.01 68.71,52.83 68.71,61.21 66.8,63.12 66.8,63.88 67.69,64.77 v2(68.28,64.77)
H_XREF_CLK1: length 125.8
  TOP w0.127: v2(66.67,21.46) 66.67,20.32 66.23,19.88 66.23,12.51 66.55,12.19 R168.2 ; v2(69.43,65.02) 69.43,69.04 69.22,69.26 69.22,73.91 70.99,75.69 R74.2 ; v2(99.78,39.24) 99.78,22.38 v2(99.19,21.78)
  LY3 w0.133: v2(99.78,39.24) 96.9,39.24 96.39,39.75 92.71,39.75 91.78,38.82 80.81,38.82 76.96,42.67 76.96,49.15 75.06,51.05 73.03,51.05 70.87,53.21 70.87,63.59 v2(69.43,65.02)
  LY4 w0.133: v2(66.67,21.46) 67.1,21.04 74.51,21.04 75.18,21.72 76.45,21.72 76.96,21.21 77.85,21.21 78.36,21.72 78.99,21.72 79.25,21.46 84.33,21.46 85.09,22.22 85.98,22.22 86.23,21.97 88.65,21.97 88.84,21.78 v2(99.19,21.78)
H_XREF_CLK3: length 39.1
  TOP w0.127: R75.2 73.14,75.56 v2(72.66,75.09)
  LY3 w0.133: v2(42.93,78.87) 42.93,75.69 47.12,71.5 63.37,71.5 65.02,73.15 v2(65.91,73.15)
  BOTTOM w0.127: v2(65.91,73.15) 66.93,73.15 68.07,74.3 71.87,74.3 v2(72.66,75.09) ; RJ29.1 43.69,79.63 v2(42.93,78.87)
HDMI_CEC_A: length 188.1
  TOP w0.127: v2(65.28,74.8) 67.18,74.8 68.29,75.91 68.29,77.35 70.57,79.63 75.2,79.63 76,80.43 76.11,80.43 78.23,82.55 80.41,82.55 81.93,84.07 84.04,84.07 84.68,84.71 U27.N25 ; v2(115.82,158.62) 115.37,158.17 U17.24
  LY4 w0.133: v2(65.28,74.8) 65.28,74.37 63.75,72.85 63.75,72.39 62.99,71.63 48.26,71.63 47.37,72.52 47.37,98.93 53.85,105.41 99.57,105.41 115.57,121.41 115.57,158.37 v2(115.82,158.62)
HDMI_CEC_B: length 14
  TOP w0.127: R27.1 112.69,155.07 112.98,154.77 113.52,154.77 v2(113.61,154.68) 113.92,154.68 113.97,154.74 U17.6
  TOP w0.14: 106.92,160.92 P1.13 v2(106.92,159.4)
  LY4 w0.133: v2(113.61,154.68) 113.57,154.73 112.48,154.73 110.11,157.1 110.11,158.12 108.2,160.02 107.54,160.02 v2(106.92,159.4)
HDMI_DSCL: length 175.8
  TOP w0.127: U17.1 v2(114.6,157.3)
  LY3 w0.133: 114.81,157.1 v2(114.6,157.3)
  LY4 w0.133: v2(114.6,157.3) 115.19,156.72 115.19,123.19 97.93,105.93 53.63,105.93 46.1,98.4 46.1,97.41 46.59,96.92 46.59,71.52 47.5,70.61 63.6,70.61 63.6,70.61 63.75,70.61 64.9,71.75 64.9,72.26 v2(65.28,72.64)
  BOTTOM w0.127: R265.1 76.71,74.8 75.69,73.79 68.33,73.79 67.18,72.64 v2(65.28,72.64) ; R212.1 v2(114.6,157.3)
HDMI_DSDA: length 179.4
  TOP w0.127: v2(113.66,156.72) 114.04,156.34 U17.2
  LY3 w0.133: 114.05,156.34 v2(113.66,156.72)
  LY4 w0.133: v2(113.66,156.72) 114.81,155.57 114.81,123.32 98.04,106.55 57.15,106.55 56.85,106.85 54.18,106.85 45.84,98.51 45.84,97.3 46.33,96.81 46.33,69.51 47.61,68.23 62.39,68.23 63.54,69.38 63.54,69.85 v2(65.91,72.22)
  BOTTOM w0.127: R266.1 76.83,73.91 76.33,73.41 68.58,73.41 67.4,72.22 v2(65.91,72.22) ; R215.1 113.79,156.59 v2(113.66,156.72)
HDMI_HPD: length 195.8
  TOP w0.127: R25.1 v2(111.25,157.1) ; U27.N23 v1(86.14,84.38)
  LY4 w0.133: v1(86.14,84.38) 84,84.38 80.97,81.35 78.04,81.35 73.15,76.45 73.14,76.45 73.13,76.45 70.35,76.45 66.67,72.76 66.67,71.88 65.36,70.57 65.36,69.81 63.27,67.71 47.39,67.71 45.81,69.29 45.81,96.6 45.32,97.09 45.32,99.26 46.27,100.2 47.17,100.2 52.66,105.7 52.66,106.64 53.13,107.11 98.09,107.11 113.79,122.81 113.79,152.91 114.17,153.29 114.17,155.83 113.75,156.25 112.1,156.25 v2(111.25,157.1)
HDMI_HPD_B: length 22.7
  TOP w0.127: R32.1 R31.2 112.52,152.78 v2(113.03,153.29) 113.79,153.29 114.04,153.54 U17.9
  TOP w0.14: P1.19 v2(109.92,162.43)
  LY4 w0.133: v2(113.03,153.29) 111.76,153.29 111.38,152.91 109.22,152.91 106.05,156.08 106.05,160.53 106.81,161.29 108.78,161.29 v2(109.92,162.43)
HDMI_SCL_B: length 11.9
  TOP w0.127: U17.7 113.95,154.34 113.88,154.26 113.44,154.26 113.4,154.31 v2(113.03,154.31) R28.1
  TOP w0.14: v2(107.92,159.38) P1.15 107.92,160.92
  LY4 w0.133: v2(113.03,154.31) 112.39,154.31 109.73,156.97 109.73,157.99 108.33,159.38 v2(107.92,159.38)
HDMI_SDA_B: length 14.2
  TOP w0.127: U17.8 113.8,153.94 113.63,153.76 v2(113.62,153.76) 113.58,153.8 112.65,153.8 112.39,153.54 R30.1
  TOP w0.14: 108.42,160.92 P1.16 v2(108.42,158.37)
  LY4 w0.133: v2(113.62,153.76) 111.29,153.76 110.24,154.81 109.6,154.81 107.82,156.59 107.82,157.77 v2(108.42,158.37)
HDMI_TX0+: length 10.5
  TOP w0.102: P1.7 103.92,160.92
  TOP w0.112: FL8.2 105.26,151.74 105.49,151.97 105.49,152.7 U9.1 105.46,153.4 105.46,156.41 104.24,157.63 104.24,159.59 103.92,159.92 P1.7
HDMI_TX0-: length 10.5
  TOP w0.102: P1.9 104.92,160.92
  TOP w0.112: FL8.3 106.07,151.74 105.84,151.97 105.84,152.7 U10.1 105.82,153.45 105.82,156.56 104.6,157.78 104.6,159.59 104.92,159.91 P1.9
HDMI_TX1+: length 10.5
  TOP w0.102: 102.42,160.92 P1.4
  TOP w0.112: P1.4 102.42,159.87 102.74,159.54 102.74,157.99 101.42,156.67 101.42,153.43 U7.1 101.42,152.7 101.42,151.97 101.19,151.74 FL7.2
HDMI_TX1-: length 10.5
  TOP w0.102: 103.42,160.92 P1.6
  TOP w0.112: FL7.3 102.01,151.74 101.78,151.97 101.78,152.7 U8.1 101.78,153.43 101.78,156.52 103.1,157.84 103.1,159.49 103.42,159.8 P1.6
HDMI_TX2+: length 9.1
  TOP w0.102: P1.1 100.91,160.92
  TOP w0.112: P1.1 100.91,159.87 101.22,159.56 101.22,158.93 98.4,156.11 98.4,155.36 U3.1 98.37,154.61 98.37,154 98.15,153.77 FL3.2
HDMI_TX2-: length 9.1
  TOP w0.102: P1.3 101.91,160.92
  TOP w0.112: P1.3 101.91,159.89 101.57,159.55 101.57,158.78 98.76,155.96 98.76,155.31 U4.1 98.73,154.61 98.73,154 98.96,153.77 FL3.3
HDMI_TXC+: length 9.1
  TOP w0.102: 105.42,160.92 P1.10
  TOP w0.112: P1.10 105.42,159.91 105.74,159.59 105.74,158.6 108.56,155.78 108.56,155.36 U5.1 108.53,154.61 108.53,154 108.31,153.77 FL4.2
HDMI_TXC-: length 9.1
  TOP w0.102: 106.42,160.92 P1.12
  TOP w0.112: P1.12 106.42,159.82 106.1,159.49 106.1,158.75 108.92,155.93 108.92,155.31 U6.1 108.89,154.61 108.89,154 109.12,153.77 FL4.3
HDRV1_N: length 20.3
  TOP w0.305: U19.28 47.88,119.89 C50.2 45.97,121.03 45.34,121.67 v2(45.34,124.33)
  BOTTOM w0.305: v2(45.34,124.33) 45.97,124.97 45.97,132.21 v2(49.78,136.02)
  vias: v2(48.01,147.19) v2(48.01,146.3) v2(48.01,145.41) v2(48.01,144.53) v2(48.01,143.64) v2(48.01,142.75) v2(48.01,141.86) v2(48.01,140.97) v2(48.01,140.08) v2(48.01,139.19) v2(48.01,138.3) v2(48.01,137.41) v2(48.89,147.19) v2(48.89,146.3) v2(48.89,145.41) v2(48.89,144.53) v2(48.89,143.64) v2(48.89,142.75) v2(48.89,141.86) v2(48.89,140.97) v2(48.89,140.08) v2(48.89,139.19) v2(48.89,138.3) v2(48.89,137.41) v2(51.31,137.92) v2(52.2,137.92) v2(53.09,137.92) v2(53.97,137.92)
HDRV1_P: length 22.5
  TOP w0.305: U19.27 49.38,121.05 v2(48.64,121.79) ; R14.2 v2(43.69,137.16)
  BOTTOM w0.305: v2(48.64,121.79) 46.35,121.79 42.93,125.22 42.93,136.4 v2(43.69,137.16)
HDRV2_N: length 17.7
  TOP w0.305: U19.18 55.23,121.02 55.75,121.54 C47.1 56.46,123.27 D7.1 56.46,126.85 D4.2 v2(57.85,126.87)
  LY4 w0.305: v2(58.67,135) 59.02,134.65 59.02,128.05 v2(57.85,126.87)
  vias: v2(55.5,137.92) v2(56.39,137.92) v2(57.28,137.92) v2(58.67,147.7) v2(58.67,146.81) v2(58.67,145.92) v2(58.67,145.03) v2(58.67,144.14) v2(58.67,143.26) v2(58.67,142.37) v2(58.67,141.48) v2(58.67,140.59) v2(58.67,139.7) v2(58.67,138.81) v2(58.67,137.92) v2(58.67,137.03) v2(59.56,147.7) v2(59.56,146.81) v2(59.56,145.92) v2(59.56,145.03) v2(59.56,144.14) v2(59.56,143.26) v2(59.56,142.37) v2(59.56,141.48) v2(59.56,140.59) v2(59.56,139.7) v2(59.56,138.81) v2(59.56,137.92)
HDRV2_P: length 23.1
  TOP w0.305: v2(54.99,121.67) 54.58,121.26 U19.19 ; R15.1 v2(66.99,136.27)
  BOTTOM w0.305: v2(66.99,136.27) 65.66,136.27 63.12,133.73 63.12,131.06 55.75,123.7 55.75,122.43 v2(54.99,121.67)
HUB0_AIN2_N: length 47.4
  TOP w0.127: U36.24 34.48,45.28 34.67,45.08 35.18,45.08 v2(35.69,44.58)
  LY3 w0.133: v2(35.69,44.58) 35.18,45.08 27.81,45.08 26.42,43.69 24.51,43.69 17.91,37.08 17.91,27.81 13.46,23.37 v2(13.46,17.14)
  BOTTOM w0.127: v2(13.46,17.14) R397.2 12.7,17.27 C531.1
HUB0_AIN2_P: length 47.4
  TOP w0.127: v2(34.96,44.58) 34.76,44.78 U36.23
  LY3 w0.133: v2(14.1,14.86) 14.1,17.4 13.84,17.65 13.84,23.24 18.29,27.69 18.29,36.96 24.64,43.31 26.54,43.31 27.81,44.58 v2(34.96,44.58)
  BOTTOM w0.127: C535.1 15.24,14.73 R398.1 v2(14.1,14.86)
HUB0_AIN3_N: length 39.1
  TOP w0.127: v2(35.68,45.59) 35.68,45.72 35.13,46.28 U36.26
  LY3 w0.133: v2(35.68,45.59) 35.68,45.6 35.18,46.1 24.77,46.1 21.34,42.67 19.18,42.67 13.84,37.34 13.84,28.83 v2(13.59,28.57)
  BOTTOM w0.127: v2(13.59,28.57) R387.2 12.7,28.7 C520.1
HUB0_AIN3_P: length 38.5
  TOP w0.127: v2(34.96,45.59) 34.78,45.78 U36.25
  LY3 w0.133: v2(14.22,26.29) 14.22,37.21 19.3,42.29 21.59,42.29 23.62,44.32 24.77,44.32 26.03,45.59 v2(34.96,45.59)
  BOTTOM w0.127: v2(14.22,26.29) R390.1 15.24,26.16 C530.1
HUB0_AIN4_N: length 33.6
  TOP w0.127: v2(35.75,46.8) 35.28,47.27 U36.28
  BOTTOM w0.127: C502.1 12.7,40.13 R359.2 15.11,40 15.62,40.51 15.62,45.47 18.54,48.39 23.75,48.39 24.55,47.59 31.53,47.59 31.88,47.24 35.31,47.24 v2(35.75,46.8)
HUB0_AIN4_P: length 31.1
  TOP w0.127: U36.27 v2(34.96,46.78)
  BOTTOM w0.127: C513.1 15.24,37.59 R361.1 16,38.61 16,45.34 18.8,48.13 23.49,48.13 24.3,47.33 31.28,47.33 31.88,46.74 34.92,46.74 v2(34.96,46.78)
HUB0_AIN5_N: length 28
  TOP w0.127: U36.30 35.16,48.28 v2(35.69,47.75)
  BOTTOM w0.127: C473.1 12.7,51.56 R318.2 15.11,51.43 16.13,50.42 23.37,50.42 25.02,48.77 31.5,48.77 32.07,48.19 35.25,48.19 v2(35.69,47.75)
HUB0_AIN5_P: length 23.6
  TOP w0.127: U36.29 v2(34.96,47.77)
  BOTTOM w0.127: v2(34.96,47.77) 34.94,47.75 32,47.75 31.24,48.51 24.77,48.51 23.24,50.04 16,50.04 R321.1 15.24,49.02 C490.1
HUB0_AIN6_N: length 36.1
  TOP w0.127: U36.32 35.18,49.28 v2(35.69,48.77)
  BOTTOM w0.127: C438.1 12.57,64.13 R301.2 15.11,62.86 17.91,60.07 17.91,56.01 20.45,53.47 30.35,53.47 31.88,51.94 31.88,49.53 32.21,49.2 35.26,49.2 v2(35.69,48.77)
HUB0_AIN6_P: length 30.8
  TOP w0.127: U36.31 v2(34.96,48.78)
  BOTTOM w0.127: v2(34.96,48.78) 34.96,48.77 32.13,48.77 31.5,49.4 31.5,51.82 30.23,53.09 20.32,53.09 17.53,55.88 17.53,59.69 16.64,60.58 R302.1 15.24,60.45 C449.1
HUB0_CLKO: length 10.4
  BOTTOM w0.127: R325.2 36.96,46.36 32.9,46.36 31.5,44.96 FB1.1
HUB_AOUT0: length 55.3
  TOP w0.127: C94.2 39.78,85.47 v2(40.13,85.12) ; v2(21.21,45.19) 21.29,45.28 U36.82
  LY3 w0.133: v2(40.13,85.12) 38.61,83.6 38.61,71.12 31.62,64.13 23.11,64.13 20.66,61.68 20.66,45.74 v2(21.21,45.19)
HUB_AOUT1: length 54.6
  TOP w0.127: U36.83 20.76,44.78 v2(20.45,45.08) ; v2(40,83.69) C99.2
  LY3 w0.133: v2(40,83.69) 38.99,82.68 38.99,70.87 31.88,63.75 24.77,63.75 21.97,60.96 21.97,45.34 21.34,44.7 20.83,44.7 v2(20.45,45.08)
HUB_AOUT2: length 51.5
  TOP w0.127: v2(40.13,81.53) 39.75,81.91 C103.2 ; U36.84 v2(21.26,44.27)
  LY3 w0.133: v2(21.26,44.27) 21.31,44.32 21.84,44.32 22.35,44.83 22.35,60.71 25.02,63.37 32,63.37 39.37,70.74 39.37,80.77 v2(40.13,81.53)
HUB_AOUT3: length 53.8
  TOP w0.127: v2(20.45,44.32) 21.44,43.33 U36.1 ; C109.2 39.75,80.14 v2(40.64,79.25)
  LY3 w0.133: v2(20.45,44.32) 20.95,43.81 21.97,43.81 22.86,44.7 22.86,60.58 25.27,62.99 32.13,62.99 39.75,70.61 39.75,78.36 v2(40.64,79.25)
I2C4_SCL: length 123
  TOP w0.127: U33.2 154.65,56.15 155.07,56.57 v2(155.07,57.4) ; v2(141.48,61.72) 141.34,61.86 U30.8 ; v2(79.76,15.49) R174.1 R181.1
  LY3 w0.133: v2(141.48,61.72) 141.99,61.72 142.74,60.97 144.91,60.97 145.42,61.47 148.33,61.47 151.38,58.42 154.05,58.42 v2(155.07,57.4) ; v2(107.19,20.45) 107.57,20.83 107.57,24.51 109.35,26.29 115.19,26.29 116.84,27.94 129.41,27.94 130.34,28.87 133.01,28.87 133.48,29.34 135.13,29.34 139.76,33.97 139.76,40.83 v2(143.7,44.77)
  LY4 w0.133: v2(143.7,44.77) 142.62,45.85 142.62,48.01 141.22,49.4 141.22,50.42 141.48,50.67 v2(141.48,61.72)
  BOTTOM w0.127: v2(107.19,20.45) 106.93,20.7 104.27,20.7 103.25,19.68 103.25,17.65 102.23,16.64 95.25,16.64 94.87,16.26 94.11,16.26 93.73,16.64 90.04,16.64 89.79,16.38 80.64,16.38 v2(79.76,15.49)
I2C4_SDA: length 121.4
  TOP w0.127: R178.1 R173.1 v2(82.93,15.49) ; v2(141.9,61.09) 141.9,61.93 141.84,62 U30.9 ; U33.1 155.15,56.09 155.57,56.52 v2(155.57,56.9)
  LY3 w0.133: v2(155.57,56.9) 155.32,56.64 154.69,56.64 153.29,58.04 151.26,58.04 148.08,61.21 145.8,61.21 145.29,60.71 142.28,60.71 v2(141.9,61.09) ; v2(104.39,19.94) 104.78,20.32 106.3,20.32 107.19,21.21 107.19,24.64 109.22,26.67 114.94,26.67 117.35,29.08 122.56,29.08 123.32,29.84 135,29.84 139.38,34.23 139.38,44.7 140.61,45.92 143.18,45.92 v2(143.64,45.47)
  LY4 w0.133: v2(141.9,61.09) 141.9,61.05 142.11,60.83 142.11,50.8 141.6,50.29 141.6,49.66 143.13,48.13 143.13,46.99 143.64,46.48 v2(143.64,45.47)
  BOTTOM w0.127: v2(104.39,19.94) 103.63,19.18 103.63,17.4 102.49,16.26 96.9,16.26 95.88,15.24 94.49,15.24 93.6,16.13 90.42,16.13 89.79,15.49 v2(82.93,15.49)
ICLINK_01_0: length 10.1
  TOP w0.127: U36.35 38.32,50.78 38.35,50.81 U34.43
ICLINK_01_1: length 10.1
  TOP w0.127: U36.36 38.59,51.28 38.61,51.3 U34.42
ICLINK_01_2: length 10.1
  TOP w0.127: U34.41 44.08,51.82 38.86,51.82 38.82,51.78 U36.37
ICLINK_01_3: length 10.1
  TOP w0.127: U34.40 44.07,52.32 39.12,52.32 39.07,52.28 U36.38
IRQ_GNSS: length 67.7
  TOP w0.127: U27.Y1 100.78,89.27 112.91,89.27 114.17,88.01 117.58,88.01 118.34,88.77 120.27,88.77 121.54,90.04 127,90.04 127.51,90.55 130.94,90.55 131.44,91.06 134.37,91.06 135,91.69 143.51,91.69 144.14,91.06 149.73,91.06 150.62,90.17 v2(152.02,90.17) ; U21.49 152.84,101.91 v2(152.78,101.85)
  LY4 w0.133: v2(152.78,101.85) 152.15,101.22 152.15,95.88 151.89,95.63 151.89,90.3 v2(152.02,90.17)
ISFSN_CHIP_01: length 21.2
  TOP w0.127: U34.32 46.88,55.61 46.48,56.01 v2(45.72,56.01) ; U36.52 v2(28.57,56.17)
  BOTTOM w0.127: v2(28.57,56.17) 29.49,55.24 39.62,55.24 40,55.63 45.34,55.63 v2(45.72,56.01)
ISFSP_CHIP_01: length 20.6
  TOP w0.127: v2(46.23,55.52) 46.23,55.5 46.38,55.35 U34.33 ; U36.53 v2(28.07,54.27)
  BOTTOM w0.127: v2(28.07,54.27) 28.66,54.86 39.88,54.86 40.26,55.24 45.95,55.24 v2(46.23,55.52)
LDOVANA: length 4.4
  TOP w0.305: U32.43 91.04,56.38 v2(91.26,56.16)
  BOTTOM w0.305: C458.1 92.28,57.01 92.28,56.31 92.13,56.16 v2(91.26,56.16)
LDRV1: length 13.6
  TOP w0.305: U19.25 50.68,121.8 v2(51.18,122.3) ; v2(56.9,128.97) R20.2
  BOTTOM w0.305: v2(56.9,128.97) 54.17,126.24 52.2,126.24 51.18,125.22 v2(51.18,122.3)
LDRV2: length 11.9
  TOP w0.305: U19.21 v2(53.28,121.99) ; R21.1 v2(58.17,128.91)
  BOTTOM w0.305: v2(58.17,128.91) 53.28,124.02 v2(53.28,121.99)
LIN_INH: length 2
  TOP w0.127: U47.8 TP53.1
LIN_WAKE: length 1.9
  TOP w0.127: TP48.1 111,34.54
MCU_CAN0_RX: length 9.9
  TOP w0.127: U37.62 127.17,43.35 126.75,42.93 126.75,41.5 124.79,39.54 124.79,38.45 124.84,38.4 124.84,35.56
